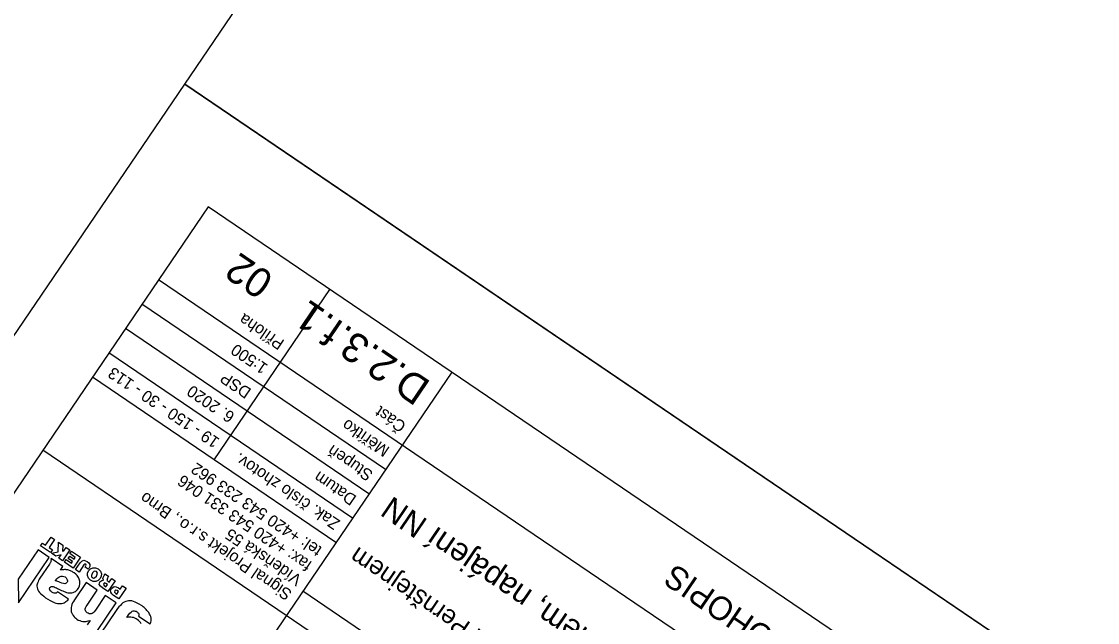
# Model space of a CAD drawing. Extents: x -620537 to -620023, y -1122866 to -1122384.
# Drawn here: x -620467.4 to -620376, y -1122552.6 to -1122501.5 of the extents above; entities that cross this region are included whole.
import ezdxf

# ---------------------------------------------------------------- set-up
doc = ezdxf.new("R2010")
doc.units = 0
for name, color, linetype in [('Info o rozpiskách', 7, 'Continuous'), ('popis', 7, 'Continuous'), ('Ramečky', 7, 'Continuous'), ('RÁMY', 7, 'Continuous'), ('Text', 7, 'Continuous'), ('Text barevný', 7, 'Continuous')]:
    doc.layers.add(name, color=color, linetype=linetype)

msp = doc.modelspace()

# ---------------------------------------------------------------- linework, layer by layer
at = {"layer": 'Info o rozpiskách'}
for points in [[(-620464.917, -1122546.661), (-620465.766, -1122546.085), (-620465.604, -1122545.845), (-620465.333, -1122546.029), (-620464.872, -1122545.35), (-620464.571, -1122545.554), (-620465.032, -1122546.233), (-620464.755, -1122546.422), (-620464.917, -1122546.661)], [(-620463.906, -1122547.348), (-620464.215, -1122547.138), (-620464.016, -1122546.845), (-620464.477, -1122546.96), (-620464.832, -1122546.719), (-620464.257, -1122546.602), (-620464.247, -1122545.774), (-620463.884, -1122546.021), (-620463.907, -1122546.535), (-620463.79, -1122546.513), (-620463.591, -1122546.22), (-620463.283, -1122546.43), (-620463.906, -1122547.348)], [(-620462.988, -1122547.972), (-620463.736, -1122547.463), (-620463.595, -1122547.255), (-620463.147, -1122547.559), (-620463.053, -1122547.42), (-620463.431, -1122547.163), (-620463.284, -1122546.947), (-620462.906, -1122547.204), (-620462.812, -1122547.065), (-620463.282, -1122546.745), (-620463.136, -1122546.529), (-620462.364, -1122547.053), (-620462.988, -1122547.972)], [(-620462.494, -1122548.307), (-620462.795, -1122548.103), (-620462.407, -1122547.531), (-620462.256, -1122547.375), (-620462.087, -1122547.309), (-620461.801, -1122547.402), (-620461.657, -1122547.522), (-620461.583, -1122547.663), (-620461.584, -1122547.831), (-620461.664, -1122548.014), (-620461.718, -1122548.078), (-620461.989, -1122547.895), (-620461.899, -1122547.73), (-620461.93, -1122547.642), (-620462.004, -1122547.636), (-620462.08, -1122547.697), (-620462.494, -1122548.307)], [(-620461.514, -1122549.006), (-620461.702, -1122548.833), (-620461.791, -1122548.616), (-620461.771, -1122548.403), (-620461.681, -1122548.205), (-620461.519, -1122548.033), (-620461.322, -1122547.942), (-620461.094, -1122547.938), (-620460.859, -1122548.041), (-620460.67, -1122548.227), (-620460.586, -1122548.452), (-620460.614, -1122548.659), (-620460.709, -1122548.865), (-620460.865, -1122549.03), (-620461.058, -1122549.113), (-620461.285, -1122549.116), (-620461.514, -1122549.006)], [(-620461.362, -1122548.782), (-620461.275, -1122548.819), (-620461.189, -1122548.81), (-620461.012, -1122548.648), (-620460.922, -1122548.416), (-620461.011, -1122548.265), (-620461.211, -1122548.243), (-620461.364, -1122548.386), (-620461.449, -1122548.611), (-620461.437, -1122548.709), (-620461.362, -1122548.782)], [(-620460.048, -1122549.968), (-620460.496, -1122549.664), (-620460.686, -1122549.512), (-620460.775, -1122549.362), (-620460.719, -1122549.129), (-620460.573, -1122549.014), (-620460.412, -1122549.01), (-620460.481, -1122548.828), (-620460.399, -1122548.659), (-620460.352, -1122548.589), (-620460.312, -1122548.514), (-620460.32, -1122548.475), (-620460.304, -1122548.452), (-620459.995, -1122548.662), (-620460.09, -1122548.835), (-620460.136, -1122549.018), (-620460.079, -1122549.068), (-620459.992, -1122549.138), (-620459.945, -1122549.169), (-620459.725, -1122548.845), (-620459.424, -1122549.05), (-620460.048, -1122549.968)], [(-620460.208, -1122549.555), (-620460.082, -1122549.37), (-620460.213, -1122549.281), (-620460.342, -1122549.238), (-620460.402, -1122549.277), (-620460.418, -1122549.367), (-620460.354, -1122549.456), (-620460.208, -1122549.555)], [(-620459.122, -1122550.597), (-620459.562, -1122550.298), (-620459.721, -1122550.168), (-620459.803, -1122550.022), (-620459.812, -1122549.869), (-620459.735, -1122549.707), (-620459.511, -1122549.543), (-620459.341, -1122549.558), (-620459.148, -1122549.655), (-620458.993, -1122549.76), (-620458.799, -1122549.474), (-620458.498, -1122549.679), (-620459.122, -1122550.597)], [(-620459.282, -1122550.184), (-620459.14, -1122549.976), (-620459.271, -1122549.887), (-620459.364, -1122549.857), (-620459.46, -1122549.916), (-620459.476, -1122550.007), (-620459.366, -1122550.127), (-620459.282, -1122550.184)]]:
    msp.add_lwpolyline(points, dxfattribs=at)
at = {"layer": 'popis'}
for points in [[(-620467.624, -1122550.912), (-620465.019, -1122547.077), (-620465.976, -1122546.427), (-620467.669, -1122548.92), (-620467.624, -1122550.912)], [(-620463.404, -1122550.61), (-620464.322, -1122549.986), (-620464.377, -1122550.05), (-620464.429, -1122550.094), (-620464.486, -1122550.111), (-620464.546, -1122550.116), (-620464.613, -1122550.115), (-620464.685, -1122550.089), (-620464.739, -1122550.052), (-620464.801, -1122550.01), (-620464.87, -1122549.963), (-620464.935, -1122549.908), (-620464.968, -1122549.841), (-620464.988, -1122549.804), (-620464.998, -1122549.752), (-620465.008, -1122549.7), (-620464.982, -1122549.662), (-620464.971, -1122549.613), (-620464.929, -1122549.585), (-620464.89, -1122549.544), (-620464.83, -1122549.539), (-620464.771, -1122549.535), (-620464.696, -1122549.54), (-620464.608, -1122549.577), (-620464.513, -1122549.619), (-620464.418, -1122549.662), (-620464.32, -1122549.717), (-620464.209, -1122549.769), (-620464.106, -1122549.817), (-620463.995, -1122549.87), (-620463.879, -1122549.914), (-620463.768, -1122549.968), (-620463.662, -1122549.994), (-620463.559, -1122550.042), (-620463.441, -1122550.066), (-620463.317, -1122550.083), (-620463.197, -1122550.073), (-620463.102, -1122550.082), (-620463.006, -1122550.057), (-620462.926, -1122550.021), (-620462.869, -1122550.003), (-620462.798, -1122549.95), (-620462.741, -1122549.898), (-620462.678, -1122549.839), (-620462.628, -1122549.783), (-620462.581, -1122549.714), (-620462.468, -1122549.497), (-620462.42, -1122549.293), (-620462.425, -1122549.086), (-620462.476, -1122548.928), (-620462.555, -1122548.762), (-620462.665, -1122548.608), (-620462.775, -1122548.488), (-620462.909, -1122548.386), (-620462.97, -1122548.344), (-620463.03, -1122548.315), (-620463.091, -1122548.273), (-620463.171, -1122548.242), (-620463.223, -1122548.218), (-620463.297, -1122548.178), (-620463.37, -1122548.152), (-620463.434, -1122548.131), (-620463.509, -1122548.125), (-620463.584, -1122548.119), (-620463.654, -1122548.105), (-620463.742, -1122548.102), (-620463.814, -1122548.109), (-620463.892, -1122548.124), (-620463.985, -1122548.128), (-620464.058, -1122548.136), (-620463.879, -1122547.84), (-620464.867, -1122547.169), (-620464.893, -1122547.207), (-620464.876, -1122547.298), (-620464.879, -1122547.352), (-620464.882, -1122547.407), (-620464.903, -1122547.438), (-620464.919, -1122547.494), (-620464.94, -1122547.525), (-620464.971, -1122547.572), (-620465.013, -1122547.633), (-620465.821, -1122548.822), (-620465.889, -1122548.922), (-620465.934, -1122549.038), (-620465.981, -1122549.141), (-620466.028, -1122549.244), (-620466.058, -1122549.337), (-620466.076, -1122549.414), (-620466.085, -1122549.51), (-620466.063, -1122549.627), (-620466.03, -1122549.728), (-620465.992, -1122549.821), (-620465.931, -1122549.931), (-620465.857, -1122550.038), (-620465.765, -1122550.134), (-620465.636, -1122550.244), (-620465.5, -1122550.359), (-620465.346, -1122550.497), (-620465.148, -1122550.62), (-620464.937, -1122550.741), (-620464.774, -1122550.818), (-620464.612, -1122550.894), (-620464.454, -1122550.945), (-620464.328, -1122550.974), (-620464.191, -1122550.988), (-620464.069, -1122550.992), (-620463.95, -1122550.983), (-620463.854, -1122550.958), (-620463.746, -1122550.93), (-620463.662, -1122550.874), (-620463.605, -1122550.823), (-620463.529, -1122550.761), (-620463.461, -1122550.694), (-620463.404, -1122550.61)], [(-620464.51, -1122549.035), (-620464.505, -1122549.027), (-620464.489, -1122549.004), (-620464.479, -1122548.989), (-620464.39, -1122548.891), (-620464.309, -1122548.788), (-620464.218, -1122548.737), (-620464.109, -1122548.676), (-620464, -1122548.648), (-620463.897, -1122548.662), (-620463.786, -1122548.681), (-620463.685, -1122548.716), (-620463.615, -1122548.763), (-620463.58, -1122548.81), (-620463.549, -1122548.864), (-620463.519, -1122548.919), (-620463.493, -1122548.981), (-620463.481, -1122549.046), (-620463.476, -1122549.106), (-620463.511, -1122549.172), (-620463.594, -1122549.263), (-620463.7, -1122549.303), (-620463.824, -1122549.286), (-620463.946, -1122549.249), (-620464.098, -1122549.191), (-620464.224, -1122549.128), (-620464.374, -1122549.082), (-620464.51, -1122549.035)], [(-620460.99, -1122553.365), (-620459.339, -1122550.934), (-620460.266, -1122550.305), (-620461.109, -1122551.547), (-620461.199, -1122551.679), (-620461.306, -1122551.786), (-620461.391, -1122551.83), (-620461.464, -1122551.871), (-620461.544, -1122551.872), (-620461.627, -1122551.861), (-620461.709, -1122551.817), (-620461.797, -1122551.78), (-620461.864, -1122551.712), (-620461.907, -1122551.66), (-620461.961, -1122551.589), (-620461.968, -1122551.517), (-620461.962, -1122551.442), (-620461.946, -1122551.351), (-620461.888, -1122551.233), (-620461.815, -1122551.125), (-620460.945, -1122549.844), (-620461.886, -1122549.204), (-620462.882, -1122550.671), (-620462.971, -1122550.802), (-620463.047, -1122550.931), (-620463.103, -1122551.062), (-620463.138, -1122551.196), (-620463.162, -1122551.315), (-620463.173, -1122551.432), (-620463.151, -1122551.548), (-620463.152, -1122551.649), (-620463.127, -1122551.745), (-620463.094, -1122551.846), (-620463.032, -1122551.922), (-620462.982, -1122552.013), (-620462.91, -1122552.106), (-620462.843, -1122552.174), (-620462.776, -1122552.242), (-620462.684, -1122552.305), (-620462.568, -1122552.384), (-620462.431, -1122552.431), (-620462.32, -1122552.484), (-620462.176, -1122552.503), (-620462.039, -1122552.518), (-620461.886, -1122552.509), (-620461.733, -1122552.466), (-620461.559, -1122552.426), (-620461.816, -1122552.804)], [(-620457.21, -1122552.696), (-620457.276, -1122552.595), (-620457.361, -1122552.503), (-620457.451, -1122552.42), (-620457.559, -1122552.346), (-620457.651, -1122552.284), (-620457.747, -1122552.242), (-620457.865, -1122552.183), (-620457.984, -1122552.159), (-620458.095, -1122552.14), (-620458.217, -1122552.136), (-620458.315, -1122552.148), (-620458.437, -1122552.178), (-620458.285, -1122551.955), (-620458.175, -1122551.793), (-620458.071, -1122551.706), (-620457.975, -1122551.647), (-620457.901, -1122551.606), (-620457.816, -1122551.596), (-620457.744, -1122551.623), (-620457.659, -1122551.647), (-620457.582, -1122551.699), (-620457.543, -1122551.726), (-620457.494, -1122551.77), (-620457.458, -1122551.817), (-620457.43, -1122551.859), (-620457.428, -1122551.905), (-620457.411, -1122551.962), (-620457.424, -1122551.998), (-620457.435, -1122552.047), (-620456.455, -1122552.713), (-620456.394, -1122552.574), (-620456.382, -1122552.458), (-620456.374, -1122552.328), (-620456.38, -1122552.222), (-620456.392, -1122552.09), (-620456.453, -1122551.981), (-620456.512, -1122551.885), (-620456.57, -1122551.755), (-620456.642, -1122551.661), (-620456.727, -1122551.57), (-620456.804, -1122551.484), (-620456.896, -1122551.387), (-620456.976, -1122551.322), (-620457.048, -1122551.262), (-620457.135, -1122551.191), (-620457.204, -1122551.144), (-620457.38, -1122551.036), (-620457.552, -1122550.942), (-620457.722, -1122550.86), (-620457.866, -1122550.807), (-620458.016, -1122550.762), (-620458.161, -1122550.742), (-620458.288, -1122550.746), (-620458.409, -1122550.777), (-620458.536, -1122550.814), (-620458.653, -1122550.87), (-620458.768, -1122550.939), (-620458.885, -1122551.029), (-620458.984, -1122551.141), (-620459.117, -1122551.254), (-620459.217, -1122551.401), (-620459.332, -1122551.571), (-620460.695, -1122553.577)]]:
    msp.add_lwpolyline(points, dxfattribs=at)
at = {"layer": 'Ramečky'}
for p, q in [((-620451.532, -1122517.275), (-620475.41, -1122552.434)), ((-620377.079, -1122567.839), (-620451.532, -1122517.275)), ((-620381.293, -1122574.044), (-620455.746, -1122523.48)), ((-620436.469, -1122539.593), (-620457.151, -1122525.548)), ((-620437.874, -1122541.661), (-620458.555, -1122527.616)), ((-620439.278, -1122543.73), (-620459.96, -1122529.684)), ((-620430.851, -1122531.321), (-620454.728, -1122566.479)), ((-620440.683, -1122545.798), (-620461.364, -1122531.752)), ((-620389.72, -1122586.452), (-620443.492, -1122549.934)), ((-620391.125, -1122588.521), (-620444.897, -1122552.002))]:
    msp.add_line(p, q, dxfattribs=at)
for points in [[(-620451.024, -1122538.775), (-620441.192, -1122524.298)], [(-620444.897, -1122552.002), (-620465.578, -1122537.957)]]:
    msp.add_lwpolyline(points, dxfattribs=at)
at = {"layer": 'RÁMY'}
for points in [[(-620370.093, -1122384.009), (-620283.231, -1122443.001), (-620366.661, -1122565.848), (-620453.523, -1122506.857)], [(-620453.523, -1122506.857), (-620106.075, -1122742.822), (-620189.505, -1122865.67), (-620536.954, -1122629.705)]]:
    msp.add_lwpolyline(points, close=True, dxfattribs=at)

# ---------------------------------------------------------------- texts
at = {"layer": 'Text'}
for s, p in [('Příloha', (-620444.981, -1122528.675)), ('1:500', (-620446.385, -1122530.744)), ('19 - 150 - 30 - 113', (-620450.484, -1122537.026)), ('DSP', (-620447.79, -1122532.812)), ('6. 2020', (-620449.194, -1122534.88)), ('Část', (-620434.64, -1122535.698)), ('Měřítko', (-620436.044, -1122537.766)), ('Stupeň', (-620437.449, -1122539.835)), ('Zak. číslo zhotov.', (-620440.258, -1122543.971)), ('tel: +420 543 233 962', (-620441.796, -1122546.251)), ('Datum', (-620438.854, -1122541.903)), ('fax: +420 543 331 046', (-620442.638, -1122547.492)), ('Signal Projekt s.r.o., Brno', (-620444.331, -1122549.969)), ('Vídeňská 55', (-620443.488, -1122548.728))]:
    msp.add_text(s, height=1, rotation=145.81812, dxfattribs=at).set_placement(p)
at = {"layer": 'Text barevný'}
for s, height, p in [('02', 2.5, (-620445.825, -1122523.166)), ('D.2.3.f.1', 2.5, (-620432.519, -1122532.203)), ('SO 06-06-02 Bystřice nad Pernštějnem, napájení NN', 1.9578, (-620385, -1122576.378)), ('Oprava zabezpečovacího zařízení v ŽST Bystřice nad Pernštejnem', 1.55893, (-620387.452, -1122580.989)), ('POLOHOPIS', 2, (-620398.864, -1122556.401))]:
    msp.add_text(s, height=height, rotation=145.81812, dxfattribs=at).set_placement(p)

doc.saveas('drawing.dxf')
